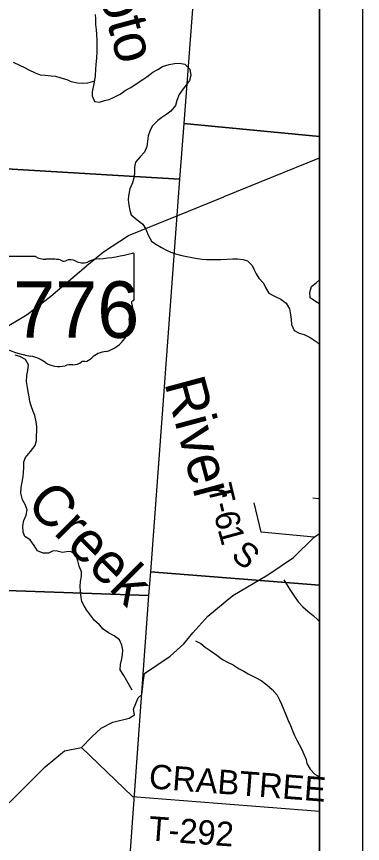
# Model space of a CAD drawing. Extents: x 0 to 40.8, y 0 to 22.
# Drawn here: x 8.193 to 9, y 17.419 to 19.348 of the extents above; entities that cross this region are included whole.
import ezdxf

# ---------------------------------------------------------------- set-up
doc = ezdxf.new("R2010")
doc.units = 0
for name, color, linetype in [('Default', 7, 'Continuous'), ('GM_X_County_Road', 7, 'Continuous'), ('GM_X_Major_River', 7, 'Continuous'), ('GM_X_Major_River_Text', 7, 'Continuous'), ('GM_X_Minor_River', 7, 'Continuous'), ('GM_X_Minor_River_Text', 7, 'Continuous'), ('GM_X_Section', 7, 'Continuous'), ('GM_X_State_Location', 7, 'Continuous'), ('GM_X_State_Route', 7, 'Continuous'), ('GM_X_State_Shield', 7, 'Continuous'), ('GM_X_Township_Road', 7, 'Continuous'), ('GM_X_Township_Road_Text', 7, 'Continuous'), ('SH_Cut_Line', 7, 'Continuous'), ('SH_Data', 7, 'Continuous')]:
    doc.layers.add(name, color=color, linetype=linetype)

msp = doc.modelspace()

# ---------------------------------------------------------------- linework, layer by layer
at = {"layer": 'Default'}
msp.add_lwpolyline([(8.9, 16.9831), (8.9, 20.9), (7.7204, 20.9), (7.7055, 20.511), (7.6192, 19.376), (7.6007, 19.1071), (7.6007, 19.1025), (7.595, 19.0259), (7.5789, 18.8336), (7.5246, 18.2047), (7.4963, 17.9476), (7.4798, 17.5479), (7.4495, 17.0841), (7.54, 17.0745), (7.7144, 17.066), (7.7161, 17.0658)], close=True, dxfattribs=at)
at = {"layer": 'GM_X_County_Road'}
for points in [[(8.9, 19.0687), (8.9, 20.1045), (8.6604, 20.121), (8.6564, 20.0646), (8.5831, 19.0989)], [(8.9, 18.022), (8.9, 19.0687), (8.5831, 19.0989), (8.5731, 18.9686), (8.5049, 18.0532)], [(8.9, 16.9825), (8.9, 18.022), (8.5049, 18.0532), (8.5005, 17.9979), (8.4297, 17.0136)]]:
    msp.add_lwpolyline(points, close=True, dxfattribs=at)
at = {"layer": 'GM_X_Major_River'}
for points in [[(8.3758, 19.3529), (8.3769, 19.3419), (8.3771, 19.3297), (8.3785, 19.3172), (8.3792, 19.307), (8.3802, 19.2918), (8.38, 19.2664), (8.3791, 19.2508), (8.3775, 19.2364), (8.377, 19.2254), (8.3761, 19.2099), (8.3741, 19.1955), (8.3694, 19.1728), (8.3689, 19.1633), (8.3749, 19.1504), (8.3862, 19.1487), (8.3976, 19.1521), (8.4086, 19.1546), (8.4192, 19.1591), (8.4341, 19.1673), (8.4485, 19.1771), (8.4596, 19.183), (8.4763, 19.1943), (8.487, 19.201), (8.4965, 19.2078), (8.511, 19.2183), (8.5227, 19.2246), (8.5334, 19.2314), (8.5486, 19.2365), (8.5615, 19.2387), (8.5728, 19.2394), (8.5857, 19.2374), (8.5969, 19.2251), (8.5995, 19.2103), (8.596, 19.1993), (8.5872, 19.1865), (8.5795, 19.1767), (8.5722, 19.1662), (8.5668, 19.1522), (8.5637, 19.1408), (8.553, 19.1276), (8.5435, 19.1201), (8.532, 19.1126), (8.5221, 19.1055), (8.5092, 19.0927), (8.5038, 19.081), (8.4999, 19.0701), (8.4986, 19.0575), (8.497, 19.0454), (8.4909, 19.0322), (8.4809, 19.0209), (8.4706, 19.0085), (8.4682, 18.9967), (8.4681, 18.9819), (8.4665, 18.9721)], [(8.4665, 18.9721), (8.463, 18.96), (8.4568, 18.9464), (8.4537, 18.9301), (8.4532, 18.9206), (8.455, 18.9081), (8.4572, 18.8959), (8.4605, 18.886), (8.4744, 18.8742), (8.4872, 18.8638), (8.4947, 18.852), (8.5002, 18.8379), (8.5077, 18.8242), (8.5175, 18.8169), (8.531, 18.8096), (8.5412, 18.8042), (8.5525, 18.7988), (8.5638, 18.7949), (8.5752, 18.7914), (8.5865, 18.789), (8.5975, 18.7867), (8.6103, 18.7843), (8.6251, 18.7826), (8.6357, 18.7818), (8.6485, 18.7813), (8.6591, 18.7812), (8.6697, 18.7815), (8.6841, 18.7822), (8.6974, 18.7828), (8.7087, 18.7827), (8.7216, 18.7811), (8.7314, 18.7783), (8.7427, 18.7673), (8.7475, 18.7577), (8.7516, 18.7478), (8.7579, 18.7379), (8.7688, 18.7265), (8.7737, 18.7158), (8.7811, 18.7032), (8.7947, 18.6959), (8.8094, 18.6889), (8.8222, 18.6797), (8.8296, 18.6664), (8.8318, 18.6523), (8.8336, 18.6413), (8.8346, 18.6299), (8.8402, 18.6155), (8.8523, 18.6097), (8.864, 18.6066), (8.8783, 18.5996), (8.8922, 18.5904), (8.9, 18.583)], [(8.8839, 18.2252), (8.8975, 18.224), (8.9, 18.2237)]]:
    msp.add_lwpolyline(points, dxfattribs=at)
at = {"layer": 'GM_X_Minor_River'}
for points in [[(8.3743, 19.1971), (8.3586, 19.1925), (8.3458, 19.1918), (8.3348, 19.1929), (8.3204, 19.1956), (8.3106, 19.2002), (8.2966, 19.2044), (8.2841, 19.2083), (8.2735, 19.2094), (8.2592, 19.2103), (8.2482, 19.2118), (8.2368, 19.216), (8.2217, 19.2229), (8.2119, 19.2282), (8.2006, 19.234), (8.1858, 19.2412)], [(8.9, 18.6778), (8.8901, 18.6833), (8.8777, 18.6924), (8.877, 18.7042), (8.8812, 18.7182), (8.8926, 18.7277), (8.9, 18.7341)], [(8.4627, 17.7767), (8.4562, 17.7881), (8.4498, 17.7984), (8.4427, 17.8113), (8.4344, 17.8246), (8.4352, 17.8367), (8.4387, 17.85), (8.4402, 17.8602), (8.441, 17.8705), (8.4384, 17.8822), (8.4328, 17.8947), (8.4207, 17.9035), (8.4071, 17.9108), (8.3946, 17.9191), (8.3863, 17.929), (8.3746, 17.9397), (8.3652, 17.9515), (8.3558, 17.964), (8.3502, 17.9739), (8.3453, 17.9834), (8.3434, 17.9933), (8.3416, 18.0073), (8.3412, 18.0198), (8.342, 18.03), (8.3443, 18.0429), (8.344, 18.0532), (8.3391, 18.0664), (8.3354, 18.0786), (8.3313, 18.0919), (8.3192, 18.1003), (8.3093, 18.0999), (8.2999, 18.0977), (8.2878, 18.1011), (8.2779, 18.1019), (8.2669, 18.0963), (8.2545, 18.0963), (8.2416, 18.102), (8.2337, 18.1146), (8.2243, 18.1275), (8.2122, 18.1355), (8.2081, 18.1458), (8.207, 18.1606), (8.2093, 18.1727), (8.2154, 18.1852), (8.2177, 18.1973), (8.2125, 18.2098), (8.2068, 18.2212), (8.2027, 18.2364), (8.2035, 18.2497), (8.2055, 18.2622), (8.2082, 18.2751), (8.2089, 18.2849), (8.2094, 18.2959), (8.2098, 18.3092), (8.2132, 18.3198), (8.2254, 18.3334), (8.2364, 18.3474), (8.2395, 18.3591), (8.2395, 18.3705), (8.2399, 18.3815), (8.2396, 18.3921), (8.2381, 18.4031), (8.2351, 18.4175), (8.2314, 18.427), (8.2269, 18.4399), (8.2239, 18.4505), (8.2221, 18.4608), (8.2195, 18.4729), (8.2184, 18.4832), (8.2157, 18.4972), (8.2166, 18.5109), (8.2189, 18.5222), (8.2204, 18.5359), (8.2133, 18.548), (8.2001, 18.5549), (8.1891, 18.558)], [(8.8164, 18.034), (8.8223, 18.0238), (8.8321, 18.0097), (8.8411, 17.9957), (8.8502, 17.9828), (8.8611, 17.9714), (8.8736, 17.9603), (8.8853, 17.9512), (8.8966, 17.9405), (8.9, 17.9363)], [(8.6105, 17.892), (8.6224, 17.8861), (8.6325, 17.8774), (8.6469, 17.8682), (8.6601, 17.8583), (8.6733, 17.8488), (8.6865, 17.8415), (8.6979, 17.8358), (8.7126, 17.827), (8.7232, 17.8209), (8.7334, 17.8148), (8.75, 17.8061), (8.7632, 17.7992), (8.7768, 17.7897), (8.7889, 17.7786), (8.8006, 17.7649), (8.8062, 17.7547), (8.8111, 17.7444), (8.8167, 17.7311), (8.822, 17.7175), (8.8265, 17.7061), (8.8321, 17.6947), (8.8359, 17.6844), (8.8415, 17.6715), (8.8471, 17.6601), (8.8524, 17.6503), (8.8584, 17.6385), (8.8633, 17.6278), (8.8682, 17.6149), (8.8704, 17.6055), (8.8776, 17.5929), (8.8892, 17.5807), (8.9, 17.575)]]:
    msp.add_lwpolyline(points, dxfattribs=at)
at = {"layer": 'GM_X_Section'}
for points in [[(7.6848, 20.077), (8.6564, 20.0646), (8.5831, 19.0989), (8.5731, 18.9686), (7.596, 19.0268)], [(7.596, 19.0268), (8.5731, 18.9686), (8.5049, 18.0532), (8.5005, 17.9979), (7.5081, 18.0324)], [(7.5081, 18.0324), (8.5005, 17.9979), (8.4297, 17.0136), (7.4523, 17.084)]]:
    msp.add_lwpolyline(points, close=True, dxfattribs=at)
at = {"layer": 'GM_X_State_Route'}
for points in [[(8.6763, 18.9278), (8.6773, 18.9282), (8.9, 19.019)], [(8.3555, 18.766), (8.357, 18.7673), (8.3952, 18.7996), (8.4541, 18.8372), (8.6763, 18.9278)], [(7.48, 17.5474), (7.9684, 17.5164), (7.9928, 17.859), (8.0065, 18.059), (8.0171, 18.336), (8.0308, 18.4575), (8.0718, 18.5354), (8.0962, 18.5668), (8.1225, 18.5953), (8.1555, 18.6155), (8.2175, 18.6534), (8.273, 18.6963), (8.3555, 18.766)]]:
    msp.add_lwpolyline(points, dxfattribs=at)
at = {"layer": 'GM_X_State_Shield'}
for p, q in [((8.2372, 18.7883), (8.1407, 18.7883)), ((8.4671, 18.6886), (8.4671, 18.7932)), ((8.467, 18.6886), (8.4671, 18.6886))]:
    msp.add_line(p, q, dxfattribs=at)
for centre, major_axis, start_param, end_param in [((8.2602, 18.8115), (0.037, 0), 4.042523, 4.731795), ((8.3497, 19.0611), (0.3495, 0), 4.814394, 5.042369), ((8.4634, 18.7937), (0.00367, 0), 6.141152, 7.989035), ((8.2725, 18.6759), (0.133, 0), 1.404758, 1.657858), ((8.3027, 18.7863), (0.0107, 0), 3.836095, 5.185415), ((8.3184, 18.7632), (0.0222, 0), 0.950623, 2.079405), ((8.347, 18.7949), (0.0267, 0), 4.081561, 5.145723), ((8.3942, 18.7272), (0.0703, 0), 1.699011, 2.107814), ((8.4662, 18.6809), (0.00568, 0), 1.883978, 3.671073), ((8.4301, 18.6676), (0.0341, 0), 5.934695, 6.695948), ((8.4631, 18.6882), (0.00393, 0), 5.05454, 6.418171), ((8.4802, 18.6447), (0.0248, 0), 2.387724, 3.262537), ((8.3692, 18.6314), (0.0874, 0), 5.101752, 6.440018), ((8.2817, 18.753), (0.2524, 0), 4.195997, 4.488961), ((8.2065, 18.4948), (0.079, 0), 0.823519, 1.323587), ((8.4061, 18.5285), (0.0479, 0), 1.647645, 2.488434), ((8.2919, 18.5722), (0.0501, 0), 4.026481, 4.996735), ((8.3245, 18.5572), (0.0267, 0), 4.691044, 5.507374), ((8.3486, 18.5378), (0.00752, 0), 1.147584, 2.315152), ((8.3454, 18.5653), (0.0282, 0), 4.937069, 5.64225), ((8.3208, 18.503), (0.0412, 0), 1.495662, 1.94098)]:
    msp.add_ellipse(centre, major_axis=major_axis, ratio=0.8, start_param=start_param, end_param=end_param, dxfattribs=at)
at = {"layer": 'GM_X_Township_Road'}
for points in [[(8.8875, 18.1341), (8.7635, 18.1458), (8.7471, 18.2142)], [(8.1753, 17.5144), (8.2047, 17.5435), (8.2596, 17.5982), (8.3049, 17.6355), (8.3445, 17.6434), (8.368, 17.6683), (8.3901, 17.6886), (8.4171, 17.7022), (8.4551, 17.7115), (8.4677, 17.7194), (8.4658, 17.7323), (8.4762, 17.7588), (8.485, 17.7671), (8.4873, 17.7853), (8.4881, 17.7952), (8.4909, 17.816), (8.551, 17.8563), (8.5834, 17.885), (8.6037, 17.9107), (8.6388, 17.9496), (8.6974, 17.9979), (8.7792, 18.0457), (8.839, 18.086), (8.8875, 18.1341), (8.9, 18.1425)], [(8.3445, 17.6434), (8.4629, 17.5286), (8.9, 17.4943)]]:
    msp.add_lwpolyline(points, dxfattribs=at)
at = {"layer": 'SH_Cut_Line'}
msp.add_lwpolyline([(8.9, 16.9831), (8.9, 20.9), (7.7204, 20.9), (7.7055, 20.511), (7.6192, 19.376), (7.6007, 19.1071), (7.6007, 19.1025), (7.595, 19.0259), (7.5789, 18.8336), (7.5246, 18.2047), (7.4963, 17.9476), (7.4798, 17.5479), (7.4495, 17.0841), (7.54, 17.0745), (7.7144, 17.066), (7.7161, 17.0658)], close=True, dxfattribs=at)
at = {"layer": 'SH_Data'}
for p, q in [((9, 21), (9, 14)), ((8.9, 20.9), (8.9, 14.1))]:
    msp.add_line(p, q, dxfattribs=at)

# ---------------------------------------------------------------- texts
at = {"layer": 'GM_X_Major_River_Text'}
for s, rotation, p in [('Scioto', 284.9983, (8.3398, 19.573)), ('River', 284.9987, (8.5372, 18.4939))]:
    msp.add_text(s, height=0.09471, rotation=rotation, dxfattribs=at).set_placement(p)
at = {"layer": 'GM_X_Minor_River_Text'}
msp.add_text('Creek', height=0.0947, rotation=314.9973, dxfattribs=at).set_placement((8.212, 18.2069))
at = {"layer": 'GM_X_State_Location'}
for s in ['s', 'r']:
    msp.add_text(s, height=0.000189, dxfattribs=at).set_placement((8.2986, 18.6715))
msp.add_text('776', height=0.000189, rotation=0, dxfattribs=at).set_placement((8.2317, 18.6577))
at = {"layer": 'GM_X_State_Shield'}
msp.add_text('776', height=0.13184, dxfattribs=at).set_placement((8.1849, 18.5988))
at = {"layer": 'GM_X_Township_Road_Text'}
for s, height, rotation, p in [('T', 0.0568, 283.4183, (8.638, 18.2515)), ('-', 0.0568, 283.4183, (8.6478, 18.2103)), ('6', 0.0568, 283.4183, (8.6532, 18.1878)), ('1', 0.0568, 285.2314, (8.6617, 18.1521)), ('S', 0.0568, 319.6931, (8.6906, 18.0876)), ('CRABTREE', 0.05682, 355.6417, (8.5001, 17.548)), ('T-292', 0.05682, 355.7731, (8.4994, 17.4266))]:
    msp.add_text(s, height=height, rotation=rotation, dxfattribs=at).set_placement(p)

doc.saveas('drawing.dxf')
